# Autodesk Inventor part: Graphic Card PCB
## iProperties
Company: Autodesk Inc.
Created: 2005-12
Part Number: Graphic Card PCB
Document SubType Name: Modeling
Designer: Autodesk Inc.
Density: 1 g/cm^3
Author: Autodesk Inc.
Title: Personal Computer
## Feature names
1. Extrusion1
2. Extrusion2
3. Extrusion3
